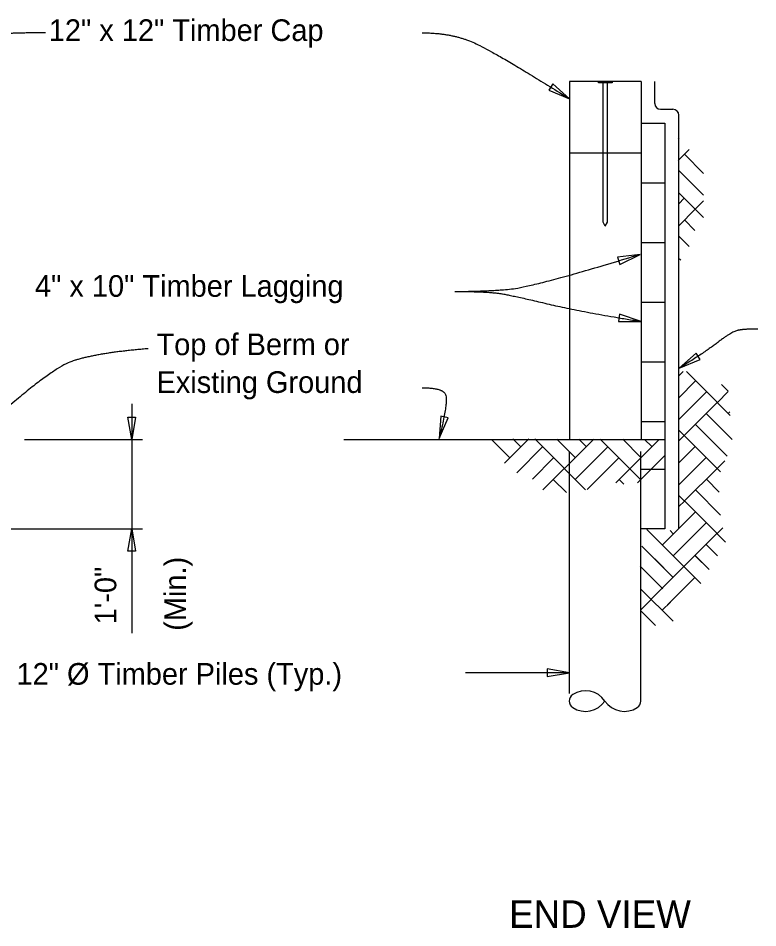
# Model space of a CAD drawing. Extents: x 10624 to 10731, y 76456 to 76513.
# Drawn here: x 10671.8 to 10682.13, y 76475.78 to 76488.48 of the extents above; entities that cross this region are included whole.
import ezdxf

# ---------------------------------------------------------------- set-up
doc = ezdxf.new("R2010")
doc.units = 0
for name, color, linetype in [('Dimension', 7, 'Continuous'), ('GroundLines', 7, 'Continuous'), ('Miscellaneous', 7, 'Continuous'), ('Patterning', 7, 'Continuous'), ('SteelMisc', 7, 'Continuous'), ('SteelMisc_h', 7, 'Continuous'), ('TextStructures', 7, 'Continuous'), ('Wood', 7, 'Continuous'), ('Wood_h', 7, 'Continuous')]:
    doc.layers.add(name, color=color, linetype=linetype)

msp = doc.modelspace()

# ---------------------------------------------------------------- linework, layer by layer
at = {"layer": 'Dimension'}
for p, q in [((10673.384, 76483.096), (10673.384, 76479.892)), ((10671.887, 76482.598), (10673.535, 76482.598)), ((10670.865, 76481.348), (10673.535, 76481.348)), ((10679.5, 76479.339), (10678.045, 76479.339))]:
    msp.add_line(p, q, dxfattribs=at)
for points in [[(10679.5, 76487.354), (10679.264, 76487.565), (10679.208, 76487.476)], [(10680.484, 76485.183), (10680.169, 76485.142), (10680.201, 76485.041)], [(10680.499, 76484.246), (10680.198, 76484.347), (10680.182, 76484.243)], [(10681.031, 76483.593), (10681.324, 76483.712), (10681.269, 76483.802)], [(10677.679, 76482.609), (10677.805, 76482.9), (10677.702, 76482.925)], [(10673.437, 76482.91), (10673.384, 76482.598), (10673.331, 76482.91)], [(10673.331, 76481.035), (10673.384, 76481.348), (10673.437, 76481.035)], [(10679.5, 76479.339), (10679.188, 76479.392), (10679.188, 76479.286)]]:
    msp.add_lwpolyline(points, close=True, dxfattribs=at)
for points in [[(10673.612, 76483.865), (10672.922, 76483.809), (10672.211, 76483.582), (10671.161, 76482.604)], [(10677.442, 76483.32), (10677.726, 76483.32), (10677.808, 76483.134), (10677.679, 76482.609)]]:
    msp.add_open_spline(points, degree=2, dxfattribs=at)
at = {"layer": 'GroundLines'}
msp.add_line((10676.348, 76482.598), (10680.498, 76482.598), dxfattribs=at)
at = {"layer": 'Miscellaneous'}
for p, q in [((10680.689, 76487.292), (10680.689, 76487.598)), ((10680.772, 76487.209), (10680.943, 76487.209)), ((10681.026, 76481.348), (10681.026, 76487.126))]:
    msp.add_line(p, q, dxfattribs=at)
for centre, start, end in [((10680.772, 76487.292), 180, 270), ((10680.943, 76487.126), 0, 90)]:
    msp.add_arc(centre, 0.0833, start, end, dxfattribs=at)
at = {"layer": 'Patterning'}
for p, q in [((10681.03, 76486.805), (10681.015, 76486.79)), ((10681.03, 76486.805), (10681.015, 76486.79)), ((10681.03, 76486.805), (10681.015, 76486.79)), ((10681.17, 76486.646), (10681.018, 76486.494)), ((10681.17, 76486.646), (10681.018, 76486.494)), ((10681.17, 76486.646), (10681.018, 76486.494)), ((10681.104, 76486.58), (10681.371, 76486.313)), ((10681.104, 76486.58), (10681.371, 76486.313)), ((10681.104, 76486.58), (10681.371, 76486.313)), ((10681.02, 76486.359), (10681.371, 76486.008)), ((10681.02, 76486.359), (10681.371, 76486.008)), ((10681.02, 76486.359), (10681.371, 76486.008)), ((10681.254, 76485.813), (10681.024, 76486.043)), ((10681.254, 76485.813), (10681.024, 76486.043)), ((10681.254, 76485.813), (10681.024, 76486.043)), ((10681.101, 76485.966), (10681.025, 76485.89)), ((10681.101, 76485.966), (10681.025, 76485.89)), ((10681.101, 76485.966), (10681.025, 76485.89)), ((10681.371, 76485.93), (10681.254, 76485.813)), ((10681.371, 76485.93), (10681.254, 76485.813)), ((10681.371, 76485.93), (10681.254, 76485.813)), ((10681.254, 76485.813), (10681.029, 76485.588)), ((10681.254, 76485.813), (10681.029, 76485.588)), ((10681.254, 76485.813), (10681.029, 76485.588)), ((10681.371, 76485.696), (10681.254, 76485.813)), ((10681.371, 76485.696), (10681.254, 76485.813)), ((10681.371, 76485.696), (10681.254, 76485.813)), ((10681.251, 76485.517), (10681.104, 76485.663)), ((10681.251, 76485.517), (10681.104, 76485.663)), ((10681.251, 76485.517), (10681.104, 76485.663)), ((10681.171, 76485.291), (10681.031, 76485.431)), ((10681.171, 76485.291), (10681.031, 76485.431)), ((10681.171, 76485.291), (10681.031, 76485.431)), ((10681.054, 76485.102), (10681.034, 76485.122)), ((10681.054, 76485.102), (10681.034, 76485.122)), ((10681.054, 76485.102), (10681.034, 76485.122)), ((10681.085, 76483.545), (10681.025, 76483.485)), ((10681.085, 76483.545), (10681.025, 76483.485)), ((10681.085, 76483.545), (10681.025, 76483.485)), ((10681.565, 76483.115), (10681.135, 76483.545)), ((10681.565, 76483.115), (10681.135, 76483.545)), ((10681.565, 76483.115), (10681.135, 76483.545)), ((10681.261, 76483.416), (10681.025, 76483.18)), ((10681.261, 76483.416), (10681.025, 76483.18)), ((10681.261, 76483.416), (10681.025, 76483.18)), ((10681.714, 76483.271), (10681.622, 76483.363)), ((10681.714, 76483.271), (10681.622, 76483.363)), ((10681.714, 76483.271), (10681.622, 76483.363)), ((10681.414, 76483.263), (10681.025, 76482.875)), ((10681.414, 76483.263), (10681.025, 76482.875)), ((10681.414, 76483.263), (10681.025, 76482.875)), ((10681.715, 76483.265), (10681.565, 76483.115)), ((10681.715, 76483.265), (10681.565, 76483.115)), ((10681.715, 76483.265), (10681.565, 76483.115)), ((10681.563, 76483.114), (10681.025, 76482.576)), ((10681.563, 76483.114), (10681.025, 76482.576)), ((10681.563, 76483.114), (10681.025, 76482.576)), ((10681.563, 76483.114), (10681.744, 76482.933)), ((10681.563, 76483.114), (10681.744, 76482.933)), ((10681.563, 76483.114), (10681.744, 76482.933)), ((10681.41, 76482.961), (10681.773, 76482.598)), ((10681.41, 76482.961), (10681.773, 76482.598)), ((10681.41, 76482.961), (10681.773, 76482.598)), ((10681.74, 76482.984), (10681.718, 76482.963)), ((10681.74, 76482.984), (10681.718, 76482.963)), ((10681.74, 76482.984), (10681.718, 76482.963)), ((10681.258, 76482.808), (10681.703, 76482.362)), ((10681.258, 76482.808), (10681.703, 76482.362)), ((10681.258, 76482.808), (10681.703, 76482.362)), ((10681.56, 76482.194), (10681.025, 76482.729)), ((10681.56, 76482.194), (10681.025, 76482.729)), ((10681.56, 76482.194), (10681.025, 76482.729)), ((10678.409, 76482.597), (10678.665, 76482.34)), ((10678.409, 76482.597), (10678.665, 76482.34)), ((10678.409, 76482.597), (10678.665, 76482.34)), ((10678.93, 76482.605), (10678.59, 76482.265)), ((10678.93, 76482.605), (10678.59, 76482.265)), ((10678.93, 76482.605), (10678.59, 76482.265)), ((10678.705, 76482.606), (10678.818, 76482.493)), ((10678.705, 76482.606), (10678.818, 76482.493)), ((10678.705, 76482.606), (10678.818, 76482.493)), ((10679.428, 76482.192), (10679.015, 76482.605)), ((10679.428, 76482.192), (10679.015, 76482.605)), ((10679.428, 76482.192), (10679.015, 76482.605)), ((10679.58, 76482.345), (10679.322, 76482.603)), ((10679.58, 76482.345), (10679.322, 76482.603)), ((10679.58, 76482.345), (10679.322, 76482.603)), ((10679.837, 76482.601), (10679.428, 76482.192)), ((10679.837, 76482.601), (10679.428, 76482.192)), ((10679.837, 76482.601), (10679.428, 76482.192)), ((10679.733, 76482.498), (10679.628, 76482.602)), ((10679.733, 76482.498), (10679.628, 76482.602)), ((10679.733, 76482.498), (10679.628, 76482.602)), ((10680.341, 76482.189), (10679.929, 76482.601)), ((10680.341, 76482.189), (10679.929, 76482.601)), ((10680.341, 76482.189), (10679.929, 76482.601)), ((10680.242, 76482.6), (10680.497, 76482.345)), ((10680.242, 76482.6), (10680.497, 76482.345)), ((10680.242, 76482.6), (10680.497, 76482.345)), ((10680.75, 76482.598), (10680.341, 76482.189)), ((10680.75, 76482.598), (10680.341, 76482.189)), ((10680.75, 76482.598), (10680.341, 76482.189)), ((10680.498, 76482.598), (10680.832, 76482.598)), ((10680.548, 76482.599), (10680.649, 76482.498)), ((10680.548, 76482.599), (10680.649, 76482.498)), ((10680.548, 76482.599), (10680.649, 76482.498)), ((10679.123, 76482.493), (10678.762, 76482.131)), ((10679.123, 76482.493), (10678.762, 76482.131)), ((10679.123, 76482.493), (10678.762, 76482.131)), ((10680.035, 76482.495), (10679.58, 76482.039)), ((10680.035, 76482.495), (10679.58, 76482.039)), ((10680.035, 76482.495), (10679.58, 76482.039)), ((10681.255, 76482.5), (10681.025, 76482.27)), ((10681.255, 76482.5), (10681.025, 76482.27)), ((10681.255, 76482.5), (10681.025, 76482.27)), ((10679.276, 76482.34), (10678.981, 76482.044)), ((10679.276, 76482.34), (10678.981, 76482.044)), ((10679.276, 76482.34), (10678.981, 76482.044)), ((10680.188, 76482.342), (10679.744, 76481.898)), ((10680.188, 76482.342), (10679.744, 76481.898)), ((10680.188, 76482.342), (10679.744, 76481.898)), ((10680.832, 76482.374), (10680.447, 76481.99)), ((10680.832, 76482.374), (10680.779, 76482.322)), ((10680.832, 76482.374), (10680.779, 76482.322)), ((10681.407, 76482.347), (10681.026, 76481.965)), ((10681.407, 76482.347), (10681.026, 76481.965)), ((10681.407, 76482.347), (10681.026, 76481.965)), ((10681.667, 76482.301), (10681.56, 76482.194)), ((10681.667, 76482.301), (10681.56, 76482.194)), ((10681.667, 76482.301), (10681.56, 76482.194)), ((10679.426, 76482.19), (10679.127, 76481.892)), ((10679.426, 76482.19), (10679.127, 76481.892)), ((10679.426, 76482.19), (10679.127, 76481.892)), ((10679.426, 76482.19), (10679.723, 76481.893)), ((10679.426, 76482.19), (10679.723, 76481.893)), ((10679.426, 76482.19), (10679.723, 76481.893)), ((10680.341, 76482.189), (10680.144, 76481.992)), ((10680.341, 76482.189), (10680.144, 76481.992)), ((10680.341, 76482.189), (10680.144, 76481.992)), ((10680.493, 76482.037), (10680.341, 76482.189)), ((10680.417, 76482.113), (10680.341, 76482.189)), ((10680.417, 76482.113), (10680.341, 76482.189)), ((10681.56, 76482.194), (10681.105, 76481.739)), ((10681.56, 76482.194), (10681.105, 76481.739)), ((10681.56, 76482.194), (10681.105, 76481.739)), ((10681.609, 76482.146), (10681.56, 76482.194)), ((10681.609, 76482.146), (10681.56, 76482.194)), ((10681.609, 76482.146), (10681.56, 76482.194)), ((10679.273, 76482.038), (10679.455, 76481.856)), ((10679.273, 76482.038), (10679.455, 76481.856)), ((10679.273, 76482.038), (10679.455, 76481.856)), ((10680.259, 76481.972), (10680.191, 76482.039)), ((10680.22, 76482.01), (10680.191, 76482.039)), ((10680.22, 76482.01), (10680.191, 76482.039)), ((10681.591, 76481.863), (10681.411, 76482.044)), ((10681.591, 76481.863), (10681.411, 76482.044)), ((10681.591, 76481.863), (10681.411, 76482.044)), ((10681.026, 76481.815), (10681.103, 76481.737)), ((10681.026, 76481.815), (10681.103, 76481.737)), ((10681.026, 76481.815), (10681.103, 76481.737)), ((10681.609, 76481.54), (10681.258, 76481.892)), ((10681.609, 76481.54), (10681.258, 76481.892)), ((10681.609, 76481.54), (10681.258, 76481.892)), ((10681.103, 76481.737), (10681.026, 76481.659)), ((10681.103, 76481.737), (10681.026, 76481.659)), ((10681.103, 76481.737), (10681.026, 76481.659)), ((10681.56, 76481.284), (10681.105, 76481.739)), ((10681.56, 76481.284), (10681.105, 76481.739)), ((10681.56, 76481.284), (10681.105, 76481.739)), ((10681.256, 76481.584), (10680.808, 76481.136)), ((10681.256, 76481.584), (10681.026, 76481.354)), ((10681.256, 76481.584), (10681.026, 76481.354)), ((10681.409, 76481.432), (10680.948, 76480.97)), ((10681.334, 76480.584), (10680.58, 76481.338)), ((10681.558, 76481.282), (10680.637, 76480.36)), ((10680.905, 76481.324), (10680.948, 76481.281)), ((10681.558, 76481.282), (10681.678, 76481.163)), ((10681.558, 76481.282), (10681.678, 76481.163)), ((10681.558, 76481.282), (10681.678, 76481.163)), ((10681.641, 76481.364), (10681.56, 76481.284)), ((10681.641, 76481.364), (10681.56, 76481.284)), ((10681.641, 76481.364), (10681.56, 76481.284)), ((10680.824, 76481.153), (10680.795, 76481.123)), ((10680.824, 76481.153), (10680.795, 76481.123)), ((10680.824, 76481.153), (10680.795, 76481.123)), ((10680.948, 76480.671), (10680.51, 76481.109)), ((10681.406, 76481.129), (10681.564, 76480.971)), ((10681.406, 76481.129), (10681.564, 76480.971)), ((10681.406, 76481.129), (10681.564, 76480.971)), ((10680.948, 76480.671), (10680.689, 76480.93)), ((10681.253, 76480.976), (10681.45, 76480.779)), ((10681.253, 76480.976), (10681.45, 76480.779)), ((10681.256, 76480.974), (10681.45, 76480.779)), ((10680.803, 76480.51), (10680.487, 76480.826)), ((10681.25, 76480.668), (10680.869, 76480.287)), ((10681.25, 76480.668), (10681.083, 76480.501)), ((10681.25, 76480.668), (10681.083, 76480.501)), ((10680.5, 76480.504), (10680.945, 76480.059)), ((10680.64, 76480.364), (10680.494, 76480.218)), ((10680.64, 76480.364), (10680.64, 76480.364)), ((10680.908, 76480.326), (10680.795, 76480.213)), ((10680.908, 76480.326), (10680.795, 76480.213)), ((10680.908, 76480.326), (10680.795, 76480.213)), ((10680.495, 76480.204), (10680.698, 76480.001))]:
    msp.add_line(p, q, dxfattribs=at)
at = {"layer": 'SteelMisc'}
msp.add_lwpolyline([(10679.906, 76487.598), (10680.093, 76487.598), (10680.093, 76487.577), (10679.906, 76487.577)], close=True, dxfattribs=at)
at = {"layer": 'SteelMisc_h'}
for p, q in [((10679.968, 76485.631), (10679.968, 76487.577)), ((10680.031, 76485.631), (10680.031, 76487.577)), ((10679.999, 76485.577), (10679.968, 76485.631)), ((10679.999, 76485.577), (10680.031, 76485.631))]:
    msp.add_line(p, q, dxfattribs=at)
at = {"layer": 'TextStructures'}
for points in [[(10672.181, 76488.277), (10671.553, 76488.277), (10671.072, 76488.197), (10670.174, 76487.605)], [(10677.443, 76488.277), (10677.839, 76488.277), (10678.441, 76488.021), (10679.5, 76487.354)], [(10677.895, 76484.665), (10678.331, 76484.665), (10679.008, 76484.73), (10680.484, 76485.183)], [(10677.895, 76484.665), (10678.366, 76484.665), (10678.742, 76484.599), (10679.666, 76484.379), (10680.499, 76484.246)], [(10682.129, 76484.14), (10681.909, 76484.14), (10681.748, 76484.09), (10681.397, 76483.819), (10681.031, 76483.593)]]:
    msp.add_open_spline(points, degree=2, dxfattribs=at)
at = {"layer": 'Wood'}
for p, q in [((10679.5, 76487.598), (10679.5, 76482.598)), ((10680.498, 76487.598), (10679.5, 76487.598)), ((10680.498, 76487.598), (10680.498, 76482.598)), ((10680.498, 76486.598), (10679.5, 76486.598))]:
    msp.add_line(p, q, dxfattribs=at)
for points in [[(10680.498, 76487.014), (10680.832, 76487.014), (10680.832, 76486.181)], [(10680.498, 76486.181), (10680.832, 76486.181), (10680.832, 76485.348)], [(10680.498, 76485.348), (10680.832, 76485.348), (10680.832, 76484.514)], [(10680.498, 76484.514), (10680.832, 76484.514), (10680.832, 76483.681)], [(10680.498, 76483.681), (10680.832, 76483.681), (10680.832, 76482.848)], [(10680.498, 76482.848), (10680.832, 76482.848), (10680.832, 76482.598)]]:
    msp.add_lwpolyline(points, dxfattribs=at)
at = {"layer": 'Wood_h'}
for p, q in [((10679.5, 76479.05), (10679.5, 76482.431)), ((10680.495, 76478.944), (10680.495, 76482.431)), ((10680.832, 76481.348), (10680.495, 76481.348))]:
    msp.add_line(p, q, dxfattribs=at)
for points in [[(10680.832, 76482.598), (10680.832, 76482.181)], [(10680.498, 76482.181), (10680.832, 76482.181), (10680.832, 76481.348)]]:
    msp.add_lwpolyline(points, dxfattribs=at)
for centre, radius, start, end in [((10679.602, 76478.944), 0.107, 122.6152, 179.9979), ((10679.723, 76478.758), 0.329, 34.3251, 123.0426), ((10679.602, 76478.944), 0.107, 179.9979, 237.3848), ((10679.723, 76479.129), 0.329, 236.955, 325.6725), ((10680.266, 76479.129), 0.329, 214.3153, 303.0328), ((10680.388, 76478.944), 0.107, 302.6152, 0.0021)]:
    msp.add_arc(centre, radius, start, end, dxfattribs=at)

# ---------------------------------------------------------------- texts
at = {"layer": 'Dimension'}
for s, p in [('(Min.)', (10674.142, 76479.925)), ('1\'-0"', (10673.168, 76480.015))]:
    msp.add_text(s, height=0.3024, rotation=90, dxfattribs=at).set_placement(p)
at = {"layer": 'TextStructures'}
for s, height, p in [('12" x 12" Timber Cap', 0.3024, (10672.225, 76488.163)), ('4" x 10" Timber Lagging', 0.3024, (10672.032, 76484.59)), ('Top of Berm or ', 0.3024, (10673.73, 76483.775)), ('Existing Ground', 0.3024, (10673.73, 76483.247)), ('12" Ø Timber Piles (Typ.)', 0.3024, (10671.774, 76479.172)), ('END VIEW', 0.384, (10678.655, 76475.776))]:
    msp.add_text(s, height=height, dxfattribs=at).set_placement(p)

doc.saveas('drawing.dxf')
